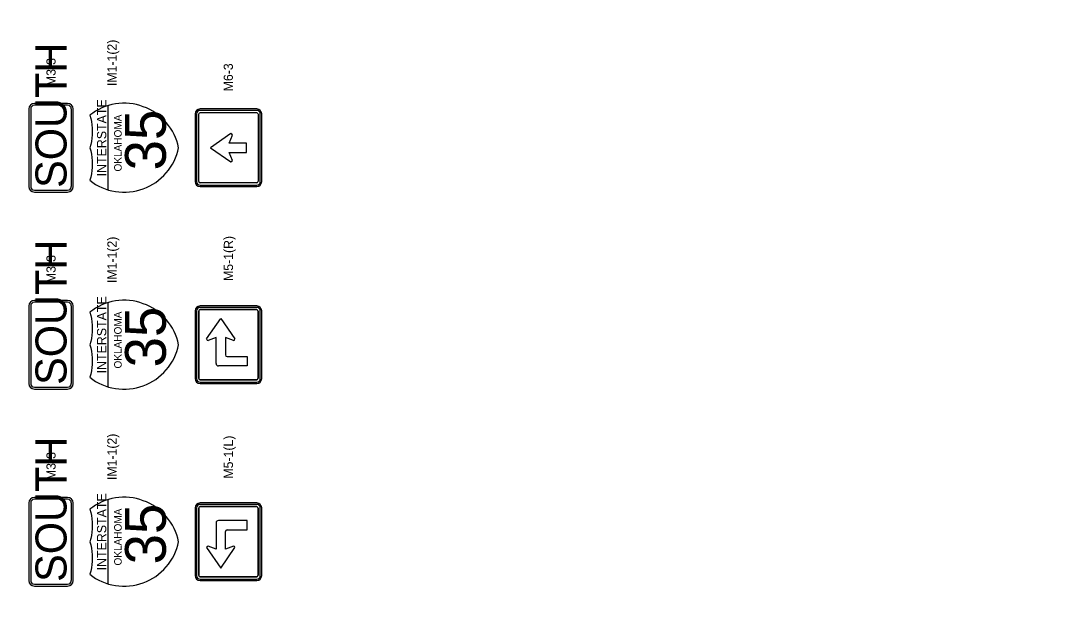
# Model space of a CAD drawing. Extents: x 2135767 to 2151731, y 141839 to 175894.
# Drawn here: x 2141240 to 2141761, y 172081 to 172373 of the extents above; entities that cross this region are included whole.
import ezdxf

# ---------------------------------------------------------------- set-up
doc = ezdxf.new("R2010")
doc.units = 0
for name, color, linetype in [('5', 7, 'Continuous'), ('6', 7, 'Continuous'), ('Default', 7, 'Continuous'), ('PR_Phasing_Detour_1', 7, 'Continuous')]:
    doc.layers.add(name, color=color, linetype=linetype)

msp = doc.modelspace()

# ---------------------------------------------------------------- linework, layer by layer
at = {"layer": '5'}
for p, q in [((2141263.96, 172330.07), (2141247.09, 172330.07)), ((2141284.59, 172287.1), (2141284.59, 172329.93)), ((2141245.21, 172328.19), (2141245.21, 172288.82)), ((2141265.84, 172288.82), (2141265.84, 172328.19)), ((2141328.65, 172325.7), (2141328.65, 172291.31)), ((2141359.91, 172328.19), (2141331.14, 172328.19)), ((2141362.4, 172291.31), (2141362.4, 172325.7)), ((2141247.09, 172286.94), (2141263.96, 172286.94)), ((2141331.14, 172288.82), (2141359.91, 172288.82)), ((2141263.96, 172230.07), (2141247.09, 172230.07)), ((2141284.59, 172187.1), (2141284.59, 172229.93)), ((2141245.21, 172228.19), (2141245.21, 172188.82)), ((2141265.84, 172188.82), (2141265.84, 172228.19)), ((2141328.65, 172225.7), (2141328.65, 172191.31)), ((2141359.91, 172228.19), (2141331.14, 172228.19)), ((2141362.4, 172191.31), (2141362.4, 172225.7)), ((2141331.14, 172188.82), (2141359.91, 172188.82)), ((2141247.09, 172186.94), (2141263.96, 172186.94)), ((2141245.21, 172128.19), (2141245.21, 172088.82)), ((2141263.96, 172130.07), (2141247.09, 172130.07)), ((2141265.84, 172088.82), (2141265.84, 172128.19)), ((2141284.59, 172087.1), (2141284.59, 172129.93)), ((2141328.65, 172125.7), (2141328.65, 172091.31)), ((2141359.91, 172128.19), (2141331.14, 172128.19)), ((2141362.4, 172091.31), (2141362.4, 172125.7)), ((2141247.09, 172086.94), (2141263.96, 172086.94)), ((2141331.14, 172088.82), (2141359.91, 172088.82))]:
    msp.add_line(p, q, dxfattribs=at)
for points in [[(2141275.21, 172291.97), (2141276.66, 172290.91), (2141278.16, 172289.93), (2141279.73, 172289.06), (2141281.35, 172288.29), (2141283.01, 172287.62), (2141284.72, 172287.06), (2141286.45, 172286.61), (2141288.21, 172286.27), (2141289.99, 172286.05), (2141291.78, 172285.94), (2141293.58, 172285.94), (2141295.36, 172286.05), (2141297.14, 172286.28), (2141298.9, 172286.63), (2141300.64, 172287.08), (2141302.34, 172287.65), (2141304, 172288.32), (2141305.62, 172289.1), (2141307.18, 172289.97), (2141308.69, 172290.95), (2141310.13, 172292.02), (2141311.49, 172293.18), (2141312.79, 172294.42), (2141314, 172295.74), (2141315.12, 172297.14), (2141316.15, 172298.61), (2141317.09, 172300.14), (2141317.92, 172301.73), (2141318.66, 172303.36), (2141319.29, 172305.04), (2141319.8, 172306.76), (2141320.21, 172308.5), (2141319.8, 172310.25), (2141319.29, 172311.97), (2141318.66, 172313.65), (2141317.92, 172315.28), (2141317.09, 172316.87), (2141316.15, 172318.4), (2141315.12, 172319.86), (2141314, 172321.26), (2141312.79, 172322.59), (2141311.49, 172323.83), (2141310.13, 172324.99), (2141308.69, 172326.06), (2141307.18, 172327.03), (2141305.62, 172327.91), (2141304, 172328.69), (2141302.34, 172329.36), (2141300.64, 172329.92), (2141298.9, 172330.38), (2141297.14, 172330.72), (2141295.36, 172330.95), (2141293.58, 172331.07), (2141291.78, 172331.07), (2141289.99, 172330.96), (2141288.21, 172330.73), (2141286.45, 172330.4), (2141284.72, 172329.95), (2141283.01, 172329.39), (2141281.35, 172328.72), (2141279.73, 172327.95), (2141278.16, 172327.07), (2141276.66, 172326.1), (2141275.21, 172325.04), (2141275.66, 172323.42), (2141276.01, 172321.78), (2141276.26, 172320.12), (2141276.41, 172318.45), (2141276.46, 172316.77), (2141276.41, 172315.09), (2141276.26, 172313.42), (2141276.01, 172311.76), (2141275.66, 172310.12), (2141275.21, 172308.5), (2141275.66, 172306.89), (2141276.01, 172305.24), (2141276.26, 172303.59), (2141276.41, 172301.91), (2141276.46, 172300.24), (2141276.41, 172298.56), (2141276.26, 172296.89), (2141276.01, 172295.23), (2141275.66, 172293.59), (2141275.21, 172291.97)], [(2141275.21, 172191.97), (2141276.66, 172190.91), (2141278.16, 172189.93), (2141279.73, 172189.06), (2141281.35, 172188.29), (2141283.01, 172187.62), (2141284.72, 172187.06), (2141286.45, 172186.61), (2141288.21, 172186.27), (2141289.99, 172186.05), (2141291.78, 172185.94), (2141293.58, 172185.94), (2141295.36, 172186.05), (2141297.14, 172186.28), (2141298.9, 172186.63), (2141300.64, 172187.08), (2141302.34, 172187.65), (2141304, 172188.32), (2141305.62, 172189.1), (2141307.18, 172189.97), (2141308.69, 172190.95), (2141310.13, 172192.02), (2141311.49, 172193.18), (2141312.79, 172194.42), (2141314, 172195.74), (2141315.12, 172197.14), (2141316.15, 172198.61), (2141317.09, 172200.14), (2141317.92, 172201.73), (2141318.66, 172203.36), (2141319.29, 172205.04), (2141319.8, 172206.76), (2141320.21, 172208.5), (2141319.8, 172210.25), (2141319.29, 172211.97), (2141318.66, 172213.65), (2141317.92, 172215.28), (2141317.09, 172216.87), (2141316.15, 172218.4), (2141315.12, 172219.86), (2141314, 172221.26), (2141312.79, 172222.59), (2141311.49, 172223.83), (2141310.13, 172224.99), (2141308.69, 172226.06), (2141307.18, 172227.03), (2141305.62, 172227.91), (2141304, 172228.69), (2141302.34, 172229.36), (2141300.64, 172229.92), (2141298.9, 172230.38), (2141297.14, 172230.72), (2141295.36, 172230.95), (2141293.58, 172231.07), (2141291.78, 172231.07), (2141289.99, 172230.96), (2141288.21, 172230.73), (2141286.45, 172230.4), (2141284.72, 172229.95), (2141283.01, 172229.39), (2141281.35, 172228.72), (2141279.73, 172227.95), (2141278.16, 172227.07), (2141276.66, 172226.1), (2141275.21, 172225.04), (2141275.66, 172223.42), (2141276.01, 172221.78), (2141276.26, 172220.12), (2141276.41, 172218.45), (2141276.46, 172216.77), (2141276.41, 172215.09), (2141276.26, 172213.42), (2141276.01, 172211.76), (2141275.66, 172210.12), (2141275.21, 172208.5), (2141275.66, 172206.89), (2141276.01, 172205.24), (2141276.26, 172203.59), (2141276.41, 172201.91), (2141276.46, 172200.24), (2141276.41, 172198.56), (2141276.26, 172196.89), (2141276.01, 172195.23), (2141275.66, 172193.59), (2141275.21, 172191.97)], [(2141275.21, 172091.97), (2141276.66, 172090.91), (2141278.16, 172089.93), (2141279.73, 172089.06), (2141281.35, 172088.29), (2141283.01, 172087.62), (2141284.72, 172087.06), (2141286.45, 172086.61), (2141288.21, 172086.27), (2141289.99, 172086.05), (2141291.78, 172085.94), (2141293.58, 172085.94), (2141295.36, 172086.05), (2141297.14, 172086.28), (2141298.9, 172086.63), (2141300.64, 172087.08), (2141302.34, 172087.65), (2141304, 172088.32), (2141305.62, 172089.1), (2141307.18, 172089.97), (2141308.69, 172090.95), (2141310.13, 172092.02), (2141311.49, 172093.18), (2141312.79, 172094.42), (2141314, 172095.74), (2141315.12, 172097.14), (2141316.15, 172098.61), (2141317.09, 172100.14), (2141317.92, 172101.73), (2141318.66, 172103.36), (2141319.29, 172105.04), (2141319.8, 172106.76), (2141320.21, 172108.5), (2141319.8, 172110.25), (2141319.29, 172111.97), (2141318.66, 172113.65), (2141317.92, 172115.28), (2141317.09, 172116.87), (2141316.15, 172118.4), (2141315.12, 172119.86), (2141314, 172121.26), (2141312.79, 172122.59), (2141311.49, 172123.83), (2141310.13, 172124.99), (2141308.69, 172126.06), (2141307.18, 172127.03), (2141305.62, 172127.91), (2141304, 172128.69), (2141302.34, 172129.36), (2141300.64, 172129.92), (2141298.9, 172130.38), (2141297.14, 172130.72), (2141295.36, 172130.95), (2141293.58, 172131.07), (2141291.78, 172131.07), (2141289.99, 172130.96), (2141288.21, 172130.73), (2141286.45, 172130.4), (2141284.72, 172129.95), (2141283.01, 172129.39), (2141281.35, 172128.72), (2141279.73, 172127.95), (2141278.16, 172127.07), (2141276.66, 172126.1), (2141275.21, 172125.04), (2141275.66, 172123.42), (2141276.01, 172121.78), (2141276.26, 172120.12), (2141276.41, 172118.45), (2141276.46, 172116.77), (2141276.41, 172115.09), (2141276.26, 172113.42), (2141276.01, 172111.76), (2141275.66, 172110.12), (2141275.21, 172108.5), (2141275.66, 172106.89), (2141276.01, 172105.24), (2141276.26, 172103.59), (2141276.41, 172101.91), (2141276.46, 172100.24), (2141276.41, 172098.56), (2141276.26, 172096.89), (2141276.01, 172095.23), (2141275.66, 172093.59), (2141275.21, 172091.97)]]:
    msp.add_lwpolyline(points, dxfattribs=at)
for centre, radius, start, end in [((2141247.09, 172328.19), 1.87, 90, 180), ((2141263.96, 172328.19), 1.87, 360, 90), ((2141331.14, 172325.7), 2.49, 90, 180), ((2141359.91, 172325.7), 2.49, 360, 90), ((2141247.09, 172288.82), 1.87, 180, 270), ((2141263.96, 172288.82), 1.87, 270, 360), ((2141331.14, 172291.31), 2.49, 180, 270), ((2141359.91, 172291.31), 2.49, 270, 360), ((2141247.09, 172228.19), 1.87, 90, 180), ((2141263.96, 172228.19), 1.87, 360, 90), ((2141331.14, 172225.7), 2.49, 90, 180), ((2141359.91, 172225.7), 2.49, 360, 90), ((2141247.09, 172188.82), 1.87, 180, 270), ((2141263.96, 172188.82), 1.87, 270, 360), ((2141331.14, 172191.31), 2.49, 180, 270), ((2141359.91, 172191.31), 2.49, 270, 360), ((2141247.09, 172128.19), 1.87, 90, 180), ((2141263.96, 172128.19), 1.87, 360, 90), ((2141331.14, 172125.7), 2.49, 90, 180), ((2141359.91, 172125.7), 2.49, 360, 90), ((2141331.14, 172091.31), 2.49, 180, 270), ((2141359.91, 172091.31), 2.49, 270, 360), ((2141247.09, 172088.82), 1.87, 180, 270), ((2141263.96, 172088.82), 1.87, 270, 360)]:
    msp.add_arc(centre, radius, start, end, dxfattribs=at)
at = {"layer": '6'}
for p, q in [((2141263.96, 172331), (2141247.09, 172331)), ((2141244.28, 172328.19), (2141244.28, 172288.82)), ((2141266.78, 172288.82), (2141266.78, 172328.19)), ((2141247.09, 172286), (2141263.96, 172286)), ((2141263.96, 172231), (2141247.09, 172231)), ((2141244.28, 172228.19), (2141244.28, 172188.82)), ((2141266.78, 172188.82), (2141266.78, 172228.19)), ((2141247.09, 172186), (2141263.96, 172186)), ((2141263.96, 172131), (2141247.09, 172131)), ((2141244.28, 172128.19), (2141244.28, 172088.82)), ((2141266.78, 172088.82), (2141266.78, 172128.19)), ((2141247.09, 172086), (2141263.96, 172086))]:
    msp.add_line(p, q, dxfattribs=at)
for centre, start, end in [((2141247.09, 172328.19), 90, 180), ((2141263.96, 172328.19), 360, 90), ((2141247.09, 172288.82), 180, 270), ((2141263.96, 172288.82), 270, 360), ((2141247.09, 172228.19), 90, 180), ((2141263.96, 172228.19), 360, 90), ((2141247.09, 172188.82), 180, 270), ((2141263.96, 172188.82), 270, 360), ((2141247.09, 172128.19), 90, 180), ((2141263.96, 172128.19), 360, 90), ((2141247.09, 172088.82), 180, 270), ((2141263.96, 172088.82), 270, 360)]:
    msp.add_arc(centre, 2.81, start, end, dxfattribs=at)
at = {"layer": 'Default'}
for p, q in [((2141329.35, 172325.7), (2141329.35, 172291.31)), ((2141329.35, 172325.7), (2141329.35, 172291.31)), ((2141330.53, 172291.31), (2141330.53, 172325.7)), ((2141330.53, 172291.31), (2141330.53, 172325.7)), ((2141359.91, 172327.49), (2141331.14, 172327.49)), ((2141359.91, 172327.49), (2141331.14, 172327.49)), ((2141331.14, 172326.32), (2141359.91, 172326.32)), ((2141331.14, 172326.32), (2141359.91, 172326.32)), ((2141360.53, 172325.7), (2141360.53, 172291.31)), ((2141360.53, 172325.7), (2141360.53, 172291.31)), ((2141361.7, 172291.31), (2141361.7, 172325.7)), ((2141361.7, 172291.31), (2141361.7, 172325.7)), ((2141346.77, 172315.69), (2141336.39, 172308.5)), ((2141345.97, 172310.9), (2141347.57, 172314.9)), ((2141336.39, 172308.5), (2141346.77, 172301.31)), ((2141354.67, 172310.9), (2141345.97, 172310.9)), ((2141354.67, 172306.11), (2141354.67, 172310.9)), ((2141347.57, 172302.11), (2141345.97, 172306.11)), ((2141345.97, 172306.11), (2141354.67, 172306.11)), ((2141359.91, 172290.69), (2141331.14, 172290.69)), ((2141359.91, 172290.69), (2141331.14, 172290.69)), ((2141331.14, 172289.52), (2141359.91, 172289.52)), ((2141331.14, 172289.52), (2141359.91, 172289.52)), ((2141329.35, 172225.7), (2141329.35, 172191.31)), ((2141329.35, 172225.7), (2141329.35, 172191.31)), ((2141330.53, 172225.7), (2141330.53, 172191.31)), ((2141330.53, 172191.31), (2141330.53, 172225.7)), ((2141359.91, 172227.49), (2141331.14, 172227.49)), ((2141359.91, 172227.49), (2141331.14, 172227.49)), ((2141359.91, 172226.32), (2141331.14, 172226.32)), ((2141331.14, 172226.32), (2141359.91, 172226.32)), ((2141360.53, 172191.31), (2141360.53, 172225.7)), ((2141360.53, 172225.7), (2141360.53, 172191.31)), ((2141361.7, 172191.31), (2141361.7, 172225.7)), ((2141361.7, 172191.31), (2141361.7, 172225.7)), ((2141334.47, 172211.48), (2141341.66, 172221.86)), ((2141341.66, 172221.86), (2141348.85, 172211.48)), ((2141339.26, 172212.27), (2141335.27, 172210.68)), ((2141339.26, 172198.93), (2141339.26, 172212.27)), ((2141348.05, 172210.68), (2141344.06, 172212.27)), ((2141344.06, 172212.27), (2141344.06, 172203.32)), ((2141344.85, 172202.53), (2141355.02, 172202.53)), ((2141355.02, 172202.53), (2141355.02, 172197.73)), ((2141355.02, 172197.73), (2141340.46, 172197.73)), ((2141331.14, 172190.69), (2141359.91, 172190.69)), ((2141359.91, 172190.69), (2141331.14, 172190.69)), ((2141331.14, 172189.52), (2141359.91, 172189.52)), ((2141331.14, 172189.52), (2141359.91, 172189.52)), ((2141329.35, 172125.7), (2141329.35, 172091.31)), ((2141329.35, 172125.7), (2141329.35, 172091.31)), ((2141330.53, 172125.7), (2141330.53, 172091.31)), ((2141330.53, 172091.31), (2141330.53, 172125.7)), ((2141359.91, 172127.49), (2141331.14, 172127.49)), ((2141359.91, 172127.49), (2141331.14, 172127.49)), ((2141359.91, 172126.32), (2141331.14, 172126.32)), ((2141331.14, 172126.32), (2141359.91, 172126.32)), ((2141360.53, 172091.31), (2141360.53, 172125.7)), ((2141360.53, 172125.7), (2141360.53, 172091.31)), ((2141361.7, 172091.31), (2141361.7, 172125.7)), ((2141361.7, 172091.31), (2141361.7, 172125.7)), ((2141339.26, 172118.08), (2141339.26, 172104.73)), ((2141355.02, 172119.27), (2141340.46, 172119.27)), ((2141355.02, 172114.48), (2141355.02, 172119.27)), ((2141344.06, 172104.73), (2141344.06, 172113.68)), ((2141344.85, 172114.48), (2141355.02, 172114.48)), ((2141334.47, 172105.53), (2141341.66, 172095.14)), ((2141339.26, 172104.73), (2141335.27, 172106.33)), ((2141341.66, 172095.14), (2141348.85, 172105.53)), ((2141348.05, 172106.33), (2141344.06, 172104.73)), ((2141331.14, 172090.69), (2141359.91, 172090.69)), ((2141359.91, 172090.69), (2141331.14, 172090.69)), ((2141331.14, 172089.52), (2141359.91, 172089.52)), ((2141331.14, 172089.52), (2141359.91, 172089.52))]:
    msp.add_line(p, q, dxfattribs=at)
for points in [[(2141346.77, 172315.69), (2141336.39, 172308.5)], [(2141347.57, 172302.11), (2141345.97, 172306.11), (2141354.67, 172306.11), (2141354.67, 172310.9), (2141345.97, 172310.9), (2141347.57, 172314.9)], [(2141336.39, 172308.5), (2141346.77, 172301.31)], [(2141334.47, 172211.48), (2141341.66, 172221.86)], [(2141341.66, 172221.86), (2141348.85, 172211.48)], [(2141339.26, 172198.93), (2141339.26, 172212.27), (2141335.27, 172210.68)], [(2141348.05, 172210.68), (2141344.06, 172212.27), (2141344.06, 172203.32)], [(2141344.85, 172202.53), (2141355.02, 172202.53), (2141355.02, 172197.73), (2141340.46, 172197.73)], [(2141339.26, 172118.08), (2141339.26, 172104.73), (2141335.27, 172106.33)], [(2141344.85, 172114.48), (2141355.02, 172114.48), (2141355.02, 172119.27), (2141340.46, 172119.27)], [(2141348.05, 172106.33), (2141344.06, 172104.73), (2141344.06, 172113.68)], [(2141334.47, 172105.53), (2141341.66, 172095.14)], [(2141341.66, 172095.14), (2141348.85, 172105.53)]]:
    msp.add_lwpolyline(points, dxfattribs=at)
for centre, radius, start, end in [((2141331.14, 172325.7), 1.79, 90, 180), ((2141331.14, 172325.7), 1.79, 90, 180), ((2141331.14, 172325.7), 0.618, 90, 180), ((2141331.14, 172325.7), 0.618, 90, 180), ((2141359.91, 172325.7), 1.79, 360, 90), ((2141359.91, 172325.7), 1.79, 360, 90), ((2141359.91, 172325.7), 0.618, 360, 90), ((2141359.91, 172325.7), 0.618, 360, 90), ((2141346.77, 172314.9), 0.799, 360, 90), ((2141346.77, 172314.9), 0.799, 360, 90), ((2141346.77, 172302.11), 0.799, 270, 360), ((2141346.77, 172302.11), 0.799, 270, 360), ((2141331.14, 172291.31), 1.79, 180, 270), ((2141331.14, 172291.31), 1.79, 180, 270), ((2141331.14, 172291.31), 0.618, 180, 270), ((2141331.14, 172291.31), 0.618, 180, 270), ((2141359.91, 172291.31), 1.79, 270, 360), ((2141359.91, 172291.31), 0.618, 270, 360), ((2141359.91, 172291.31), 1.79, 270, 360), ((2141359.91, 172291.31), 0.618, 270, 360), ((2141331.14, 172225.7), 1.79, 90, 180), ((2141331.14, 172225.7), 1.79, 90, 180), ((2141331.14, 172225.7), 0.618, 90, 180), ((2141331.14, 172225.7), 0.618, 90, 180), ((2141359.91, 172225.7), 1.79, 360, 90), ((2141359.91, 172225.7), 1.79, 360, 90), ((2141359.91, 172225.7), 0.618, 360, 90), ((2141359.91, 172225.7), 0.618, 360, 90), ((2141335.27, 172211.48), 0.799, 180, 270), ((2141335.27, 172211.48), 0.799, 180, 270), ((2141348.05, 172211.48), 0.799, 270, 360), ((2141348.05, 172211.48), 0.799, 270, 360), ((2141340.46, 172198.93), 1.2, 180, 270), ((2141340.46, 172198.93), 1.2, 180, 270), ((2141344.85, 172203.32), 0.799, 180, 270), ((2141344.85, 172203.32), 0.799, 180, 270), ((2141331.14, 172191.31), 1.79, 180, 270), ((2141331.14, 172191.31), 1.79, 180, 270), ((2141331.14, 172191.31), 0.618, 180, 270), ((2141331.14, 172191.31), 0.618, 180, 270), ((2141359.91, 172191.31), 1.79, 270, 360), ((2141359.91, 172191.31), 0.618, 270, 360), ((2141359.91, 172191.31), 1.79, 270, 360), ((2141359.91, 172191.31), 0.618, 270, 360), ((2141331.14, 172125.7), 1.79, 90, 180), ((2141331.14, 172125.7), 1.79, 90, 180), ((2141331.14, 172125.7), 0.618, 90, 180), ((2141331.14, 172125.7), 0.618, 90, 180), ((2141359.91, 172125.7), 1.79, 360, 90), ((2141359.91, 172125.7), 1.79, 360, 90), ((2141359.91, 172125.7), 0.618, 360, 90), ((2141359.91, 172125.7), 0.618, 360, 90), ((2141340.46, 172118.08), 1.2, 90, 180), ((2141340.46, 172118.08), 1.2, 90, 180), ((2141344.85, 172113.68), 0.799, 90, 180), ((2141344.85, 172113.68), 0.799, 90, 180), ((2141335.27, 172105.53), 0.799, 90, 180), ((2141335.27, 172105.53), 0.799, 90, 180), ((2141348.05, 172105.53), 0.799, 360, 90), ((2141348.05, 172105.53), 0.799, 360, 90), ((2141331.14, 172091.31), 1.79, 180, 270), ((2141331.14, 172091.31), 1.79, 180, 270), ((2141331.14, 172091.31), 0.618, 180, 270), ((2141331.14, 172091.31), 0.618, 180, 270), ((2141359.91, 172091.31), 1.79, 270, 360), ((2141359.91, 172091.31), 0.618, 270, 360), ((2141359.91, 172091.31), 1.79, 270, 360), ((2141359.91, 172091.31), 0.618, 270, 360)]:
    msp.add_arc(centre, radius, start, end, dxfattribs=at)
at = {"layer": 'PR_Phasing_Detour_1'}
msp.add_circle((2140069.54, 171591.41), 4302.23, dxfattribs=at)

# ---------------------------------------------------------------- texts
at = {"layer": 'Default'}
for s, height, p in [('SOUTH', 15.75, (2141263.4, 172288.13)), ('IM1-1(2)', 4.664, (2141288.78, 172339.82)), ('M3-3', 4.664, (2141257.85, 172339.82)), ('M6-3', 4.664, (2141347.79, 172337.15)), ('INTERSTATE', 4.704, (2141283.56, 172293.96)), ('OKLAHOMA', 3.812, (2141291.36, 172296.46)), ('35', 20.7, (2141313.78, 172297.02)), ('IM1-1(2)', 4.664, (2141288.78, 172239.82)), ('M5-1(R)', 4.664, (2141347.86, 172240.87)), ('SOUTH', 15.75, (2141263.4, 172188.13)), ('M3-3', 4.664, (2141257.85, 172239.82)), ('INTERSTATE', 4.704, (2141283.56, 172193.96)), ('OKLAHOMA', 3.812, (2141291.36, 172196.46)), ('35', 20.7, (2141313.78, 172197.02)), ('IM1-1(2)', 4.664, (2141288.78, 172139.82)), ('M5-1(L)', 4.664, (2141347.86, 172140.56)), ('SOUTH', 15.75, (2141263.4, 172088.13)), ('M3-3', 4.664, (2141257.85, 172139.82)), ('INTERSTATE', 4.704, (2141283.56, 172093.96)), ('35', 20.7, (2141313.78, 172097.02)), ('OKLAHOMA', 3.812, (2141291.36, 172096.46))]:
    msp.add_text(s, height=height, rotation=90, dxfattribs=at).set_placement(p)

doc.saveas('drawing.dxf')
